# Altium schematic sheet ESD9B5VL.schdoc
size 127 x 101 mm
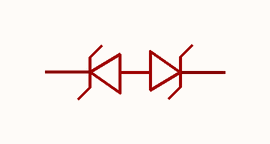
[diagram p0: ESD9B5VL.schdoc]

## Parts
D?  esd9b5vl_c2827544  [DFN1006-2L-BI]  (value not drawn)

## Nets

Not connected (* = marked no-connect by the designer): D? 1 2

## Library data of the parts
D? = esd9b5vl_c2827544: 极性:双向;反向截止电压(Vrwm):5V;钳位电压:12V;峰值脉冲电流(Ipp):3A@8/20us;峰值脉冲功率(Ppp):35W@8/20us;击穿电压(VBR):8.4V;; Manufacturer: TECH PUBLIC(台舟); AddInBom: yes; ModelId: 2bdbcca3b35b49c5a8ae725a08658930; ModelTransform: 40.1574,24.4094,0,0,0,0,0,0,0; Polarity: 双向; Reverse Stand-Off Voltage (Vrwm): 5V; Clamping Voltage: 12V; Voltage - Breakdown: 8.4V; Reverse Leakage Current (Ir): 80nA; Number of Channels: 单路; level of protection: IEC 61000-4-5；IEC 61000-4-2; Type: ESD; Junction Capacitance: 5pF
